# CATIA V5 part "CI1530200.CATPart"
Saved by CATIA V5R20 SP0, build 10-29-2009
Part number: CI1530200
Bounding box of the stored display mesh (mm): x -29 to 29, y -25.332 to 245, z -36.193 to 33.549
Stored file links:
  C:\Users\Raffaele\Desktop\3D X SITO CF\BOLEX\19-INCLINED ASSEMBLY REF_CI\CI1530200.CATPart

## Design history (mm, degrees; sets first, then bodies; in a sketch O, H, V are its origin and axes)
Set1
  DatumSurface1 to DatumSurface16 "MANIFOLD_SOLID_BREP #397"
  DatumSurface17 to DatumSurface39 "MANIFOLD_SOLID_BREP #1146"
Body1 (main body)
